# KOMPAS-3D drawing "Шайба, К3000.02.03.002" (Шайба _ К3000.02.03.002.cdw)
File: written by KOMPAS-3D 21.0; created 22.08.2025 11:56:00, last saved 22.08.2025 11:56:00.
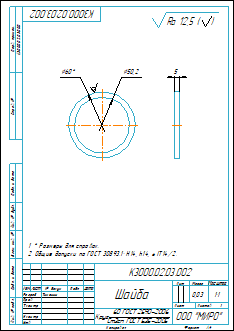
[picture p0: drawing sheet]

Sheet 1: A4, portrait

Document properties: Автор: Lutik; Полное имя файла: C:\Users\Lutik\YandexDisk\Документы\Новая папка\Бабка задняя\2D\Опора_К3000.02.03.000\Шайба _ К3000.02.03.002.cdw; Знак неуказанной шероховатости: 4; Параметр неуказанной шероховатости: Ra 12,5; Масса: 0.033292

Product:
- Part/product: Шайба  | designation К3000.02.03.002
    Материал: Круг$d60 ГОСТ 2590-2006;Ст3сп ГОСТ 535-2005$ (density 7850 kg/m3)
    Масса: 0.033292

Title block, sheet 1: Наименование: Шайба; designation: К3000.02.03.002; Материал: Круг 60 ГОСТ 2590-2006 Ст3сп ГОСТ 535-2005; Масса: 0,03; Количество листов документа: 1; organisation: ООО "МИРО"; Форматы листов документа: A4; Разработал: Тимонин

Views: Вид 1, Слева, Проекционный вид 2
Referenced files in C:\Users\Lutik\YandexDisk\Документы\Новая папка\Бабка задняя\3D\: Шайба_21.m3d
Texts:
  Ra 12,5
  Ra 12,5 ( )
  К3000.02.03.002 Шайба
Dimensions and other numbers on the sheet: 60; 50,2; 5; 1:1; 1; 0,03

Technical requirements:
  * Размеры для справок.
  Общие допуски по ГОСТ 30893.1: Н14, h14, ± IT14/2.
